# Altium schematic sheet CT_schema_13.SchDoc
size 667 x 506 mm
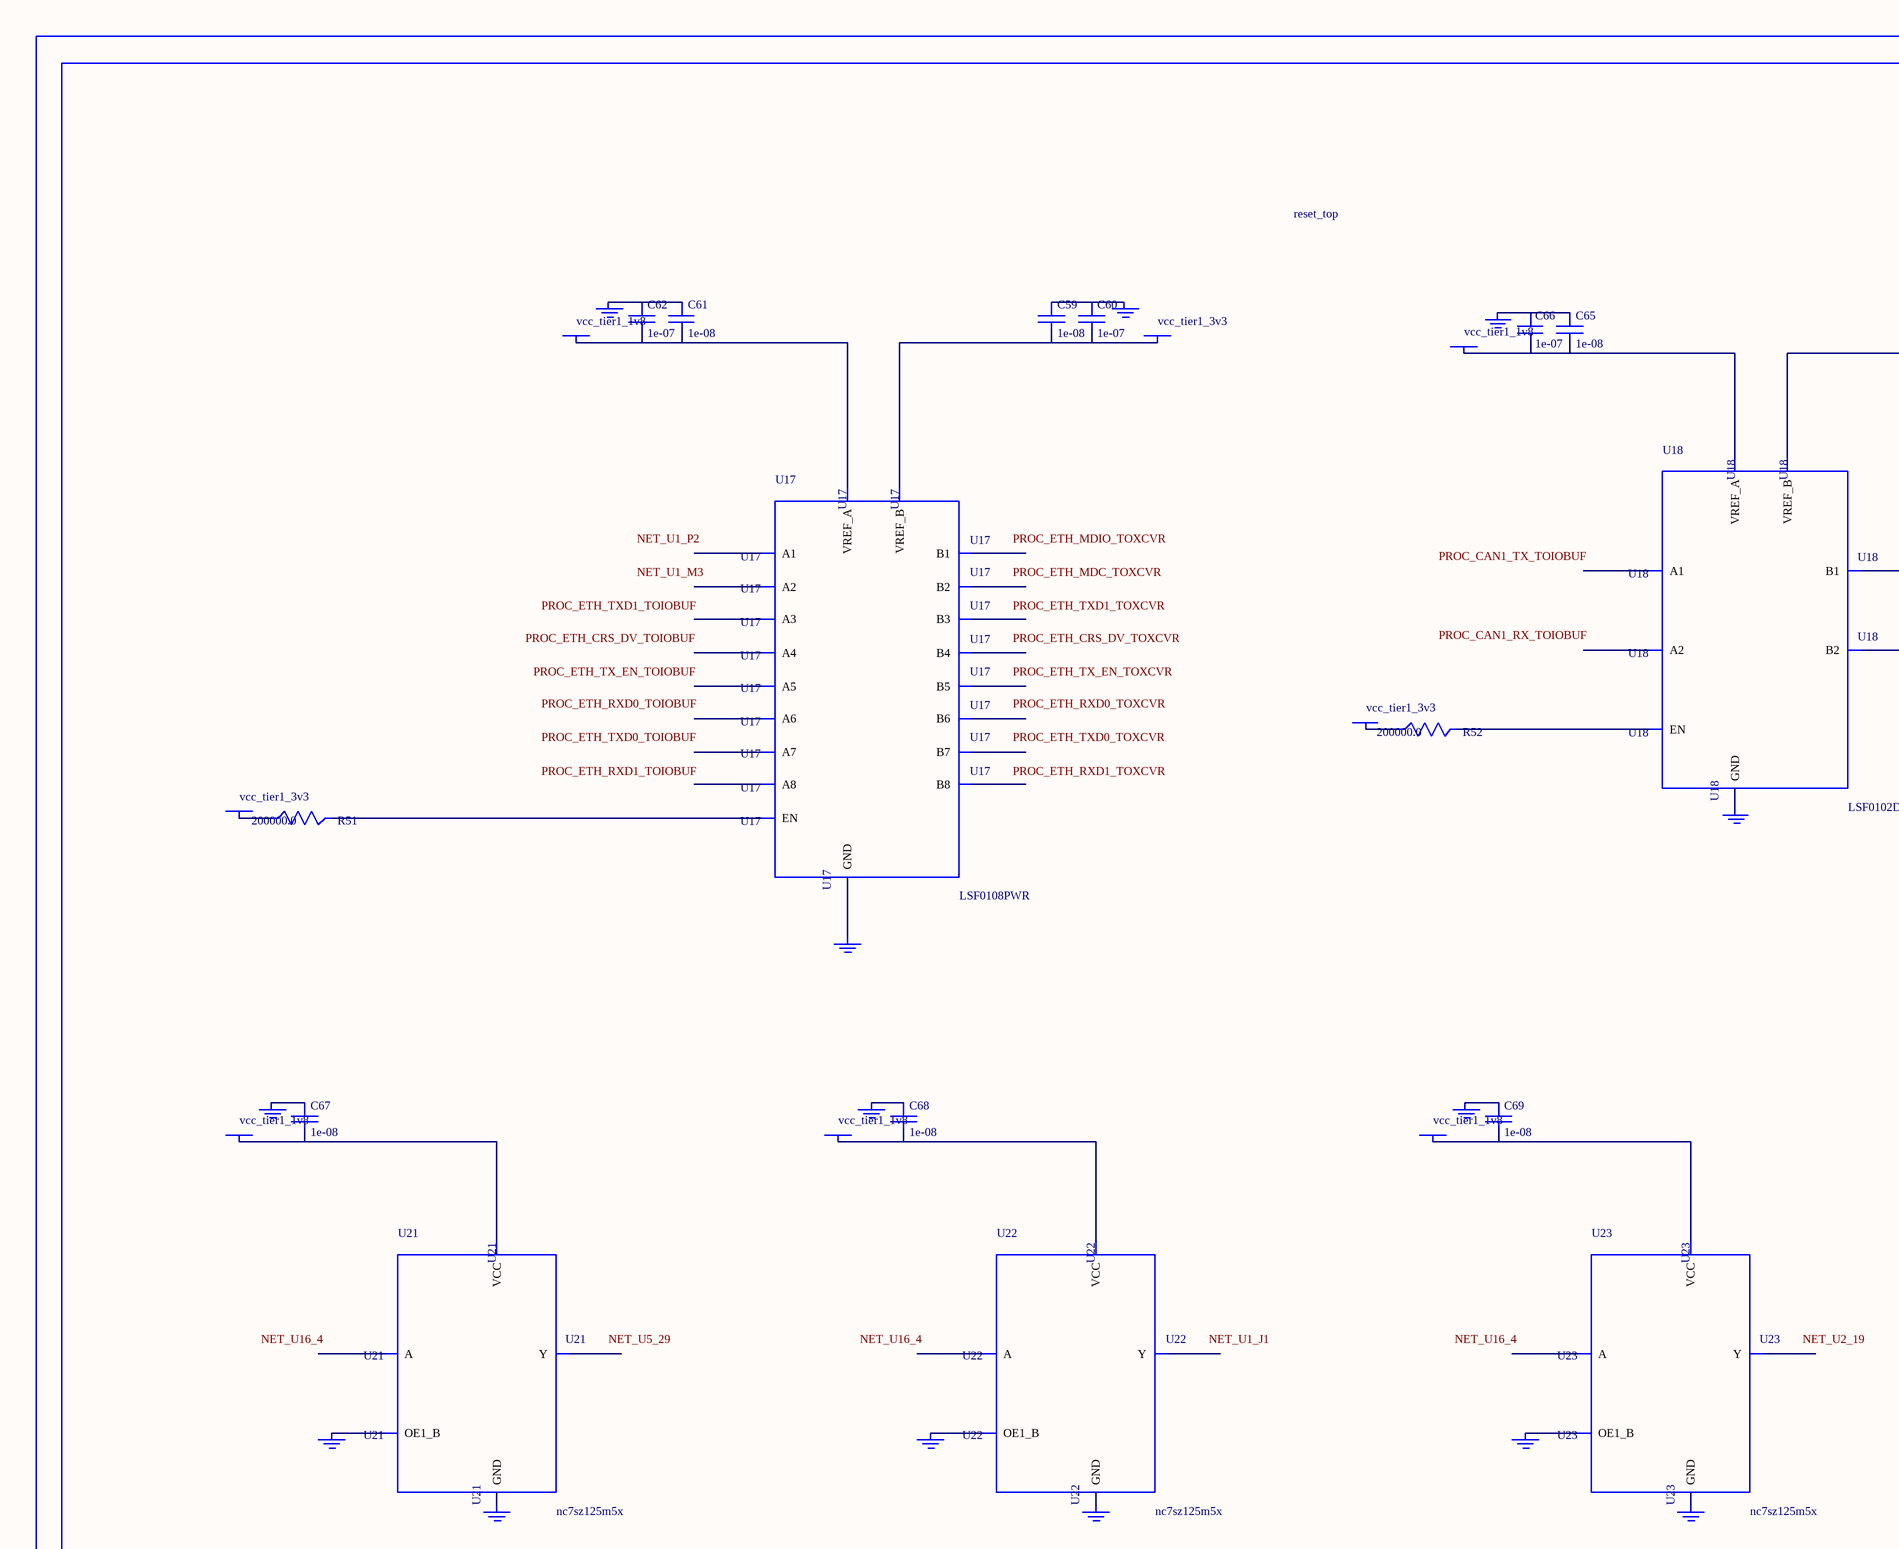
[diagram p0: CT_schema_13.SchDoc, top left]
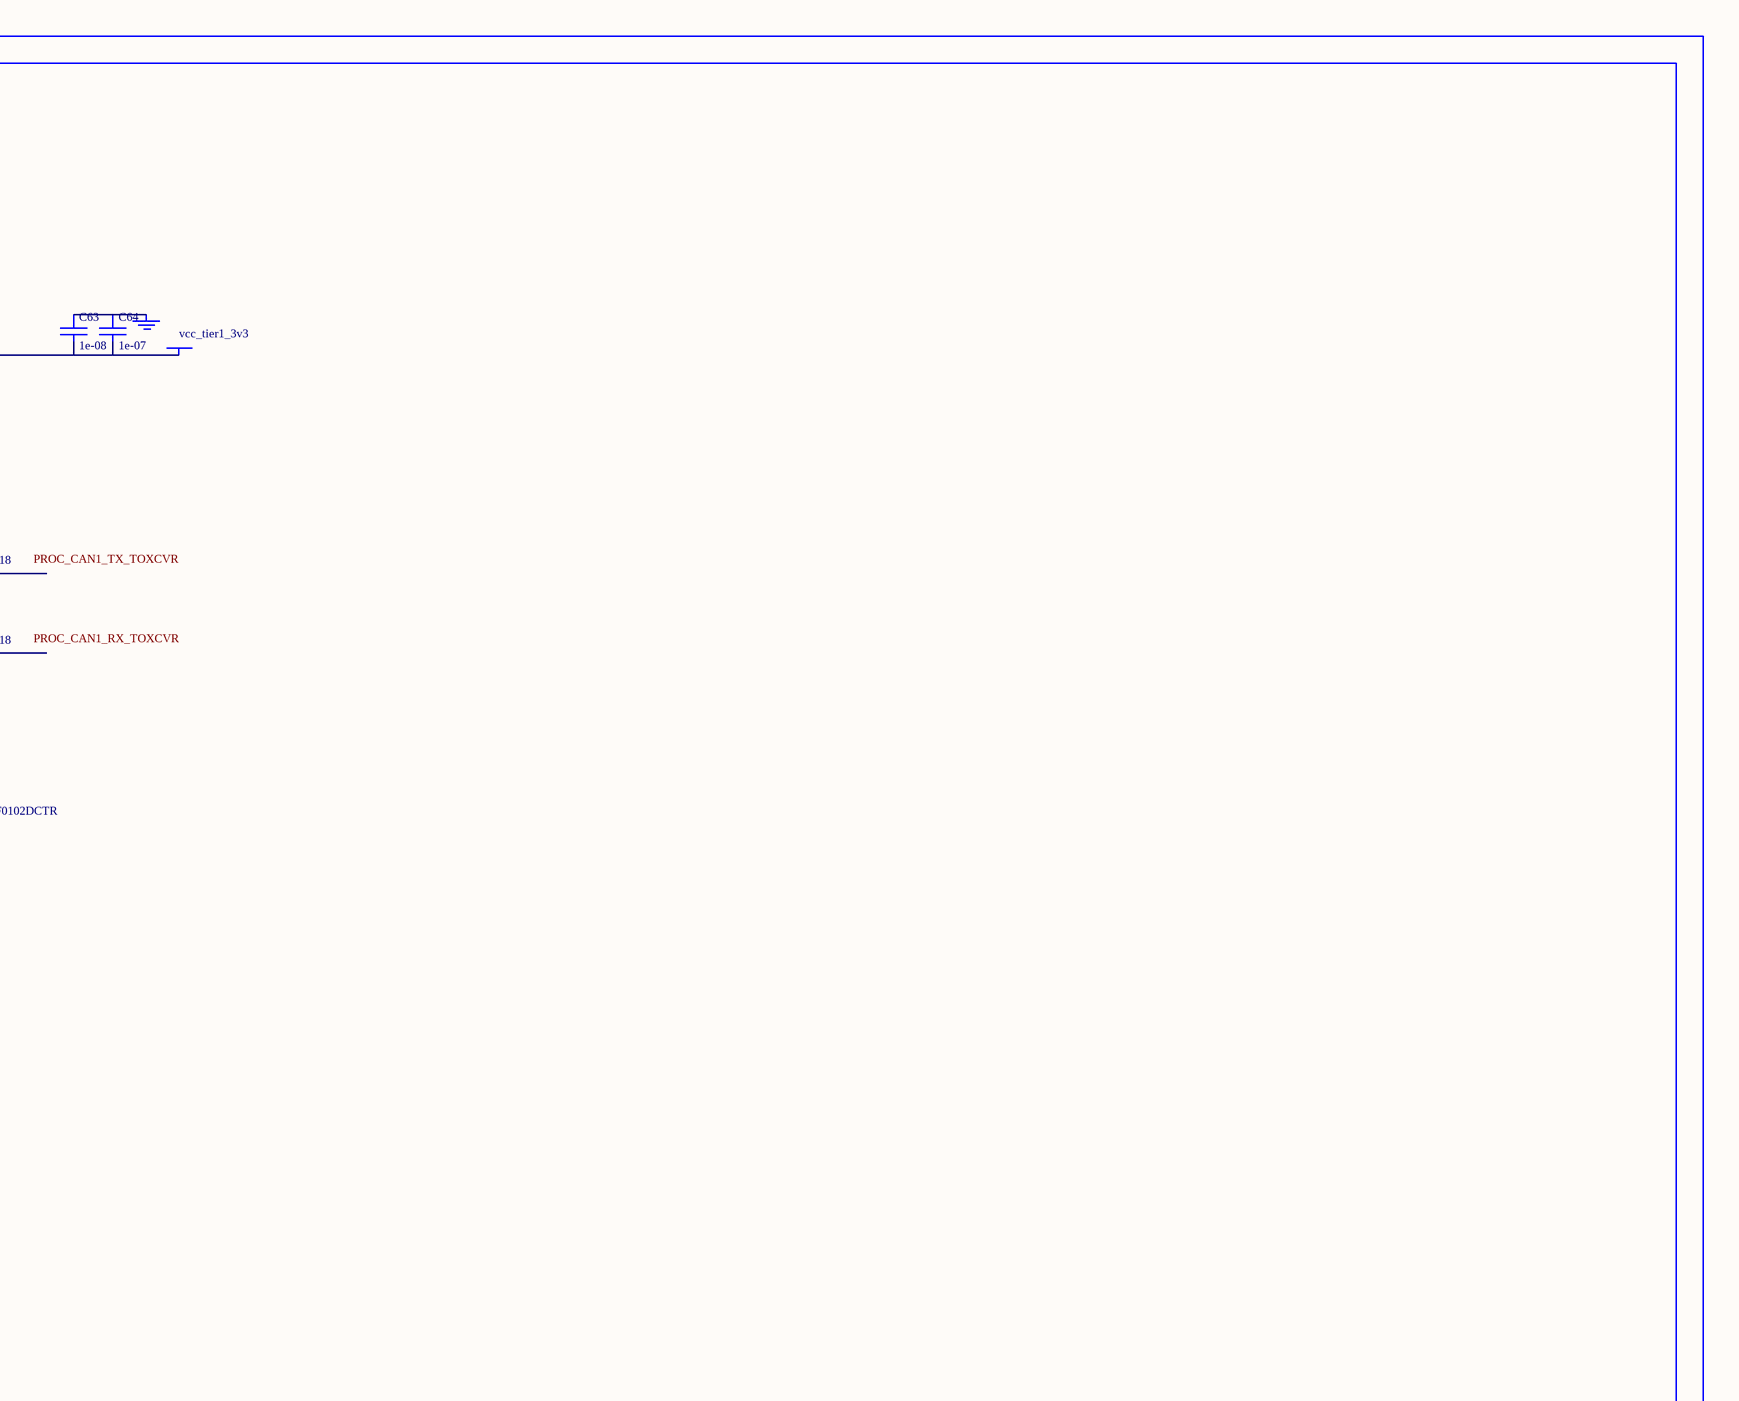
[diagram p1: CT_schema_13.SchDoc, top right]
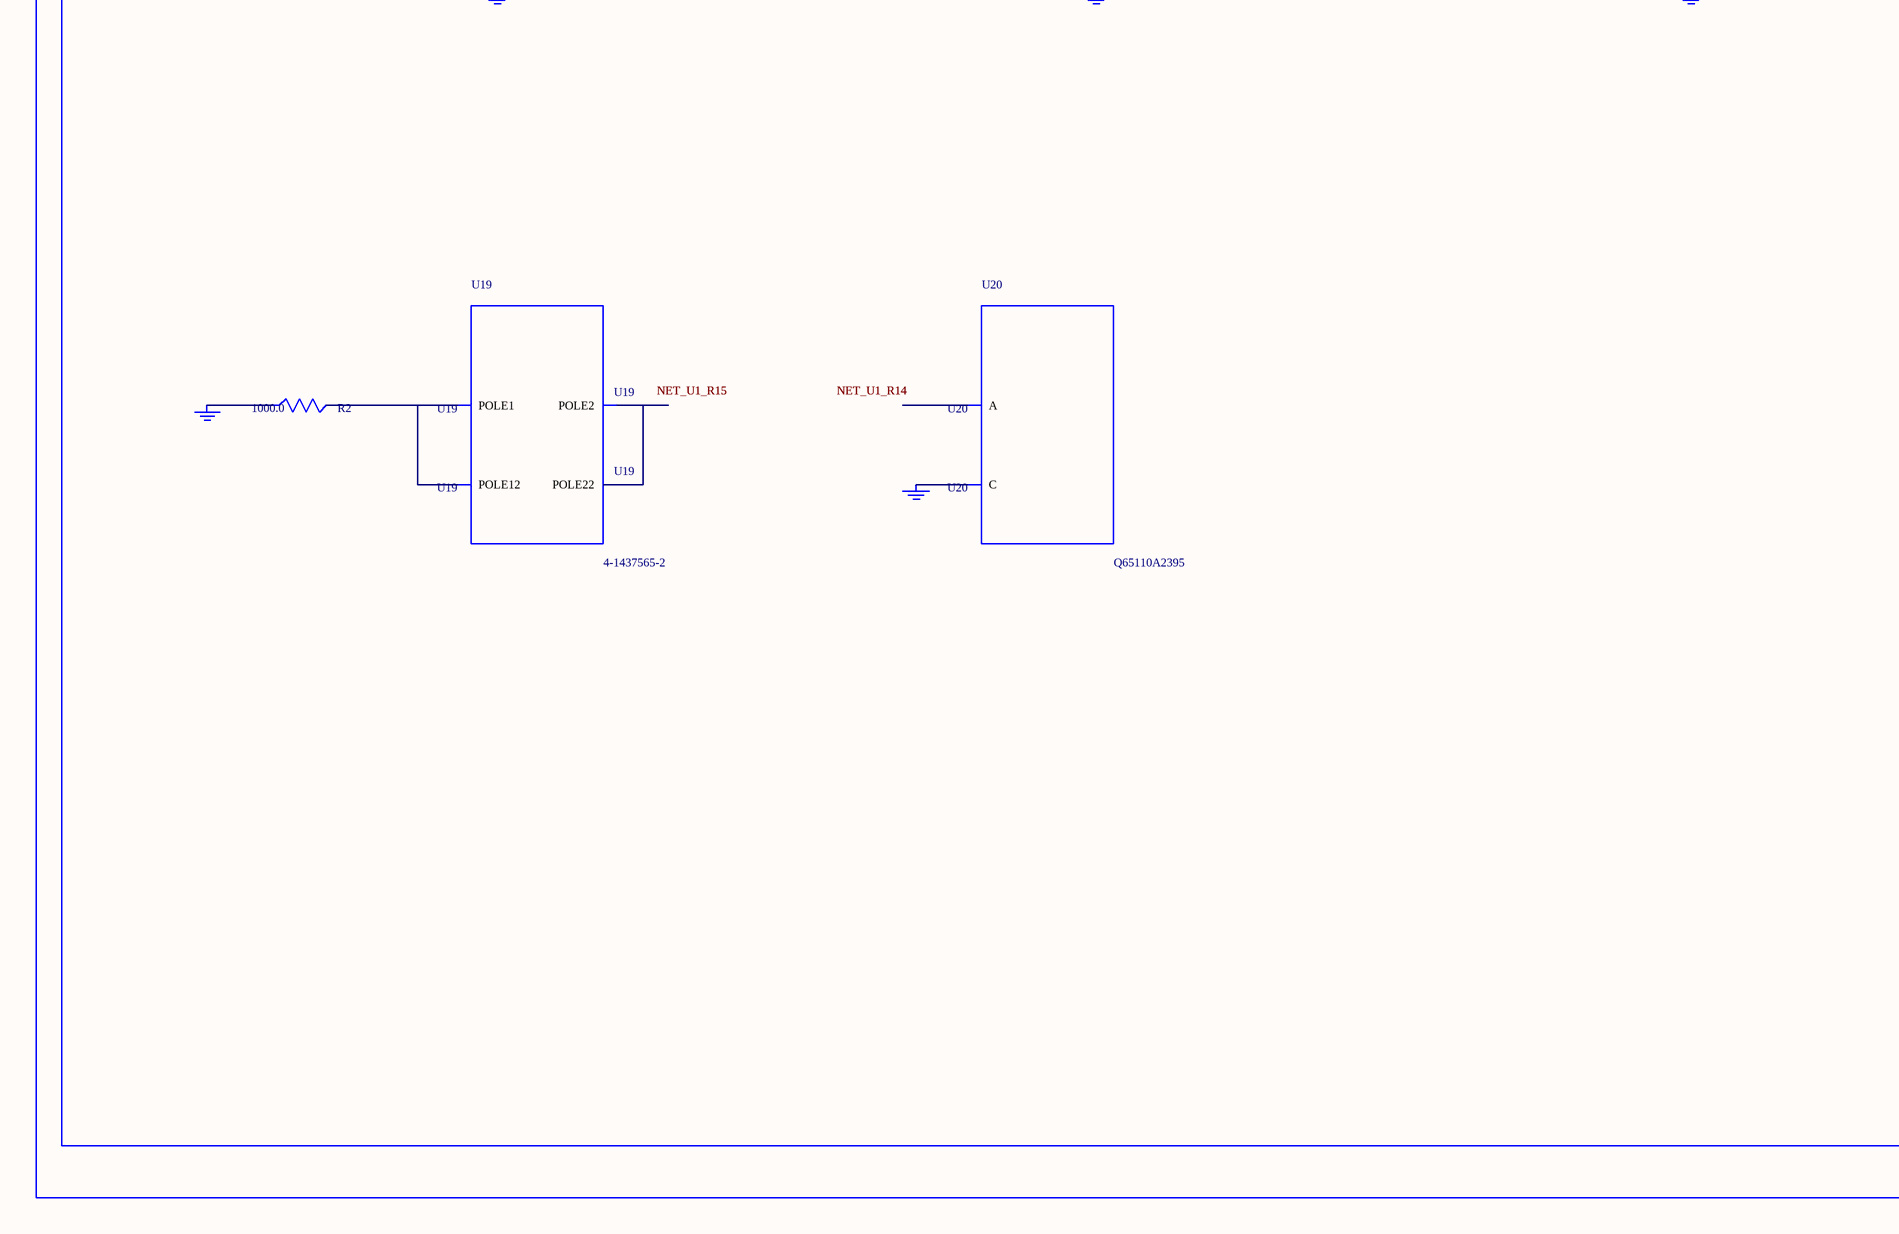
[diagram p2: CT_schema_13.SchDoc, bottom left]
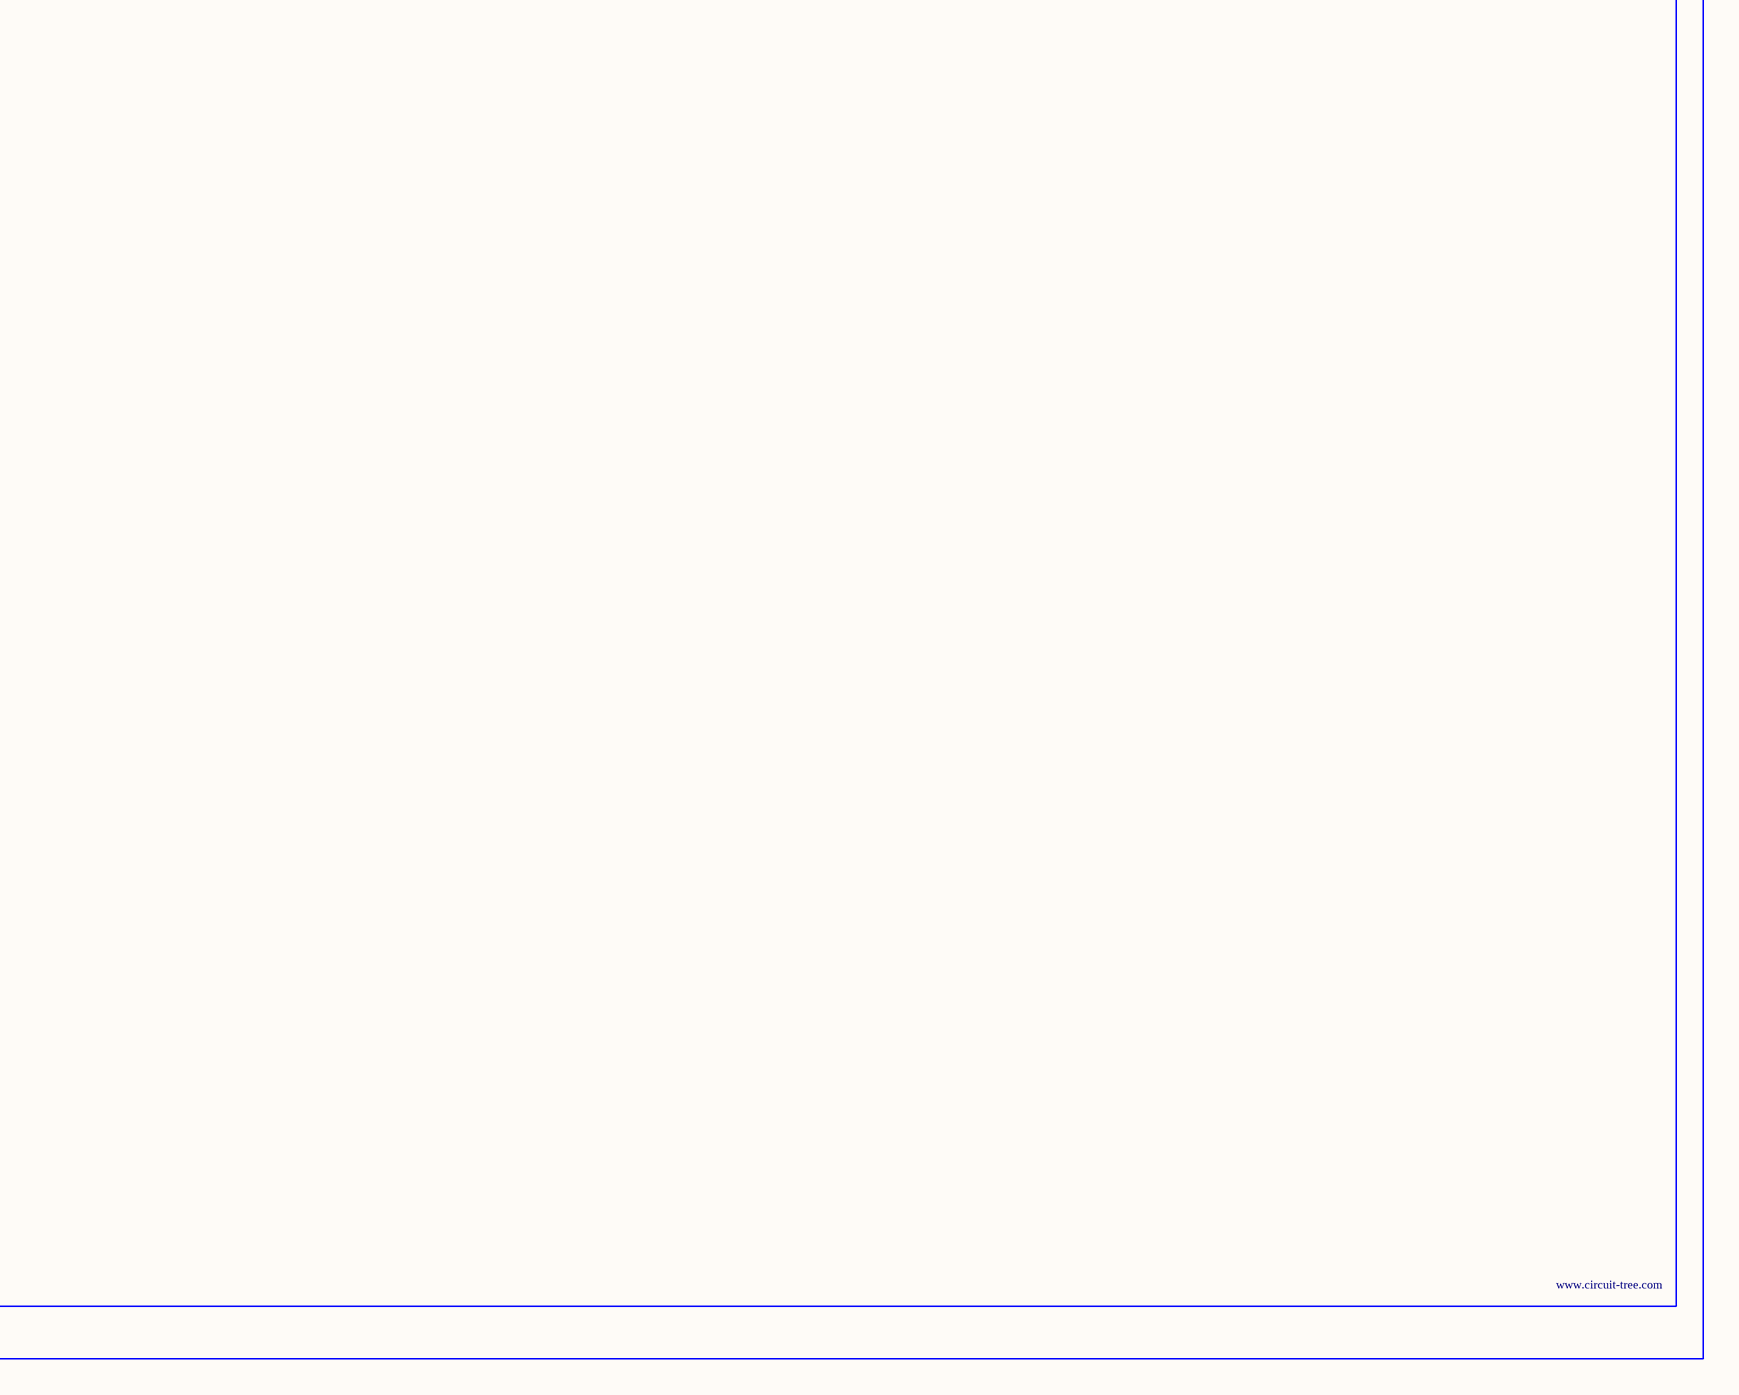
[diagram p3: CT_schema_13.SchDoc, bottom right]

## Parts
BORDER12  (no value)
C59  1e-08  [C0402]
C60  1e-07  [C0402]
C61  1e-08  [C0402]
C62  1e-07  [C0402]
C63  1e-08  [C0402]
C64  1e-07  [C0402]
C65  1e-08  [C0402]
C66  1e-07  [C0402]
C67  1e-08  [C0402]
C68  1e-08  [C0402]
C69  1e-08  [C0402]
GND_INSTANCE_12_0  (no value)
GND_INSTANCE_12_1  (no value)
GND_INSTANCE_12_2  (no value)
GND_INSTANCE_12_3  (no value)
GND_INSTANCE_12_4  (no value)
GND_INSTANCE_12_5  (no value)
GND_INSTANCE_12_6  (no value)
GND_INSTANCE_12_7  (no value)
GND_INSTANCE_12_8  (no value)
GND_INSTANCE_12_9  (no value)
GND_INSTANCE_12_10  (no value)
GND_INSTANCE_12_11  (no value)
GND_INSTANCE_12_12  (no value)
GND_INSTANCE_12_13  (no value)
GND_INSTANCE_12_14  (no value)
GND_INSTANCE_12_15  (no value)
GND_INSTANCE_12_16  (no value)
POWER_INSTANCE_12_0  vcc_tier1_1v8
POWER_INSTANCE_12_1  vcc_tier1_3v3
POWER_INSTANCE_12_2  vcc_tier1_3v3
POWER_INSTANCE_12_3  vcc_tier1_1v8
POWER_INSTANCE_12_4  vcc_tier1_3v3
POWER_INSTANCE_12_5  vcc_tier1_3v3
POWER_INSTANCE_12_6  vcc_tier1_1v8
POWER_INSTANCE_12_7  vcc_tier1_1v8
POWER_INSTANCE_12_8  vcc_tier1_1v8
R2  1000.0  [R0603]
R51  200000.0  [R0603]
R52  200000.0  [R0603]
U17  LSF0108PWR  [PW0020A]
U18  LSF0102DCTR  [DCU0008A_N]
U19  4-1437565-2  [SW_4-1437565-2]
U20  Q65110A2395  [LGM67K-G1J2-24-Z]
U21  nc7sz125m5x  [NC7SZ125M5X]
U22  nc7sz125m5x  [NC7SZ125M5X]
U23  nc7sz125m5x  [NC7SZ125M5X]

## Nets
NetC59_1: C59.1 C60.1 GND_INSTANCE_12_1.0(GND)
NetC59_2: C59.2 C60.2 POWER_INSTANCE_12_1.0(PWR) U17.19(VREF_B)
NetC61_1: C61.1 C62.1 GND_INSTANCE_12_0.0(GND)
NetC61_2: C61.2 C62.2 POWER_INSTANCE_12_0.0(PWR) U17.2(VREF_A)
NetC63_1: C63.1 C64.1 GND_INSTANCE_12_4.0(GND)
NetC63_2: C63.2 C64.2 POWER_INSTANCE_12_4.0(PWR) U18.7(VREF_B)
NetC65_1: C65.1 C66.1 GND_INSTANCE_12_3.0(GND)
NetC65_2: C65.2 C66.2 POWER_INSTANCE_12_3.0(PWR) U18.2(VREF_A)
NetC67_1: C67.1 GND_INSTANCE_12_8.0(GND)
NetC67_2: C67.2 POWER_INSTANCE_12_6.0(PWR) U21.5(VCC)
NetC68_1: C68.1 GND_INSTANCE_12_11.0(GND)
NetC68_2: C68.2 POWER_INSTANCE_12_7.0(PWR) U22.5(VCC)
NetC69_1: C69.1 GND_INSTANCE_12_14.0(GND)
NetC69_2: C69.2 POWER_INSTANCE_12_8.0(PWR) U23.5(VCC)
NetGND_INSTANCE_12_2_0: GND_INSTANCE_12_2.0(GND) U17.1(GND)
NetGND_INSTANCE_12_5_0: GND_INSTANCE_12_5.0(GND) U18.1(GND)
NetGND_INSTANCE_12_6_0: GND_INSTANCE_12_6.0(GND) R2.1
NetGND_INSTANCE_12_7_0: GND_INSTANCE_12_7.0(GND) U20.C
NetGND_INSTANCE_12_9_0: GND_INSTANCE_12_9.0(GND) U21.1(OE1_B)
NetGND_INSTANCE_12_10_0: GND_INSTANCE_12_10.0(GND) U21.3(GND)
NetGND_INSTANCE_12_12_0: GND_INSTANCE_12_12.0(GND) U22.1(OE1_B)
NetGND_INSTANCE_12_13_0: GND_INSTANCE_12_13.0(GND) U22.3(GND)
NetGND_INSTANCE_12_15_0: GND_INSTANCE_12_15.0(GND) U23.1(OE1_B)
NetGND_INSTANCE_12_16_0: GND_INSTANCE_12_16.0(GND) U23.3(GND)
NetPOWER_INSTANCE_12_2_0: POWER_INSTANCE_12_2.0(PWR) R51.1
NetPOWER_INSTANCE_12_5_0: POWER_INSTANCE_12_5.0(PWR) R52.1
NetR2_2: R2.2 U19.1(POLE1) U19.2(POLE12)
NetR51_2: R51.2 U17.20(EN)
NetR52_2: R52.2 U18.8(EN)
NetU19_3: U19.3(POLE2) U19.4(POLE22)

Not connected (* = marked no-connect by the designer): U17 3(A1) 4(A2) 5(A3) 6(A4) 7(A5) 8(A6) 9(A7) 10(A8) 11(B8) 12(B7) 13(B6) 14(B5) 15(B4) 16(B3) 17(B2) 18(B1); U18 3(A1) 4(A2) 5(B2) 6(B1); U20 A; U21 2(A) 4(Y); U22 2(A) 4(Y); U23 2(A) 4(Y)

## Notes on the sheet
- Labels drawn without touching a wire or pin: NET_U1_J1, NET_U1_M3, NET_U1_P2, NET_U2_19, NET_U5_29, NET_U16_4, PROC_CAN1_RX_TOIOBUF, PROC_CAN1_RX_TOXCVR, PROC_CAN1_TX_TOIOBUF, PROC_CAN1_TX_TOXCVR, PROC_ETH_CRS_DV_TOIOBUF, PROC_ETH_CRS_DV_TOXCVR, PROC_ETH_MDC_TOXCVR, PROC_ETH_MDIO_TOXCVR, PROC_ETH_RXD0_TOIOBUF, PROC_ETH_RXD0_TOXCVR, PROC_ETH_RXD1_TOIOBUF, PROC_ETH_RXD1_TOXCVR, PROC_ETH_TX_EN_TOIOBUF, PROC_ETH_TX_EN_TOXCVR, PROC_ETH_TXD0_TOIOBUF, PROC_ETH_TXD0_TOXCVR, PROC_ETH_TXD1_TOIOBUF, PROC_ETH_TXD1_TOXCVR

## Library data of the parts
BORDER12 = BORDER_PAGE12
C59 C61 C63 C65 C67-C69 = C0402C103K3RAC
C60 C62 C64 C66 = C0402C104K3RACTU
GND_INSTANCE_12_0-GND_INSTANCE_12_16 = GND
POWER_INSTANCE_12_0-POWER_INSTANCE_12_8 = PWR
R2 = RC0603JR-071KL
R51 R52 = RC0603JR-07200KL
